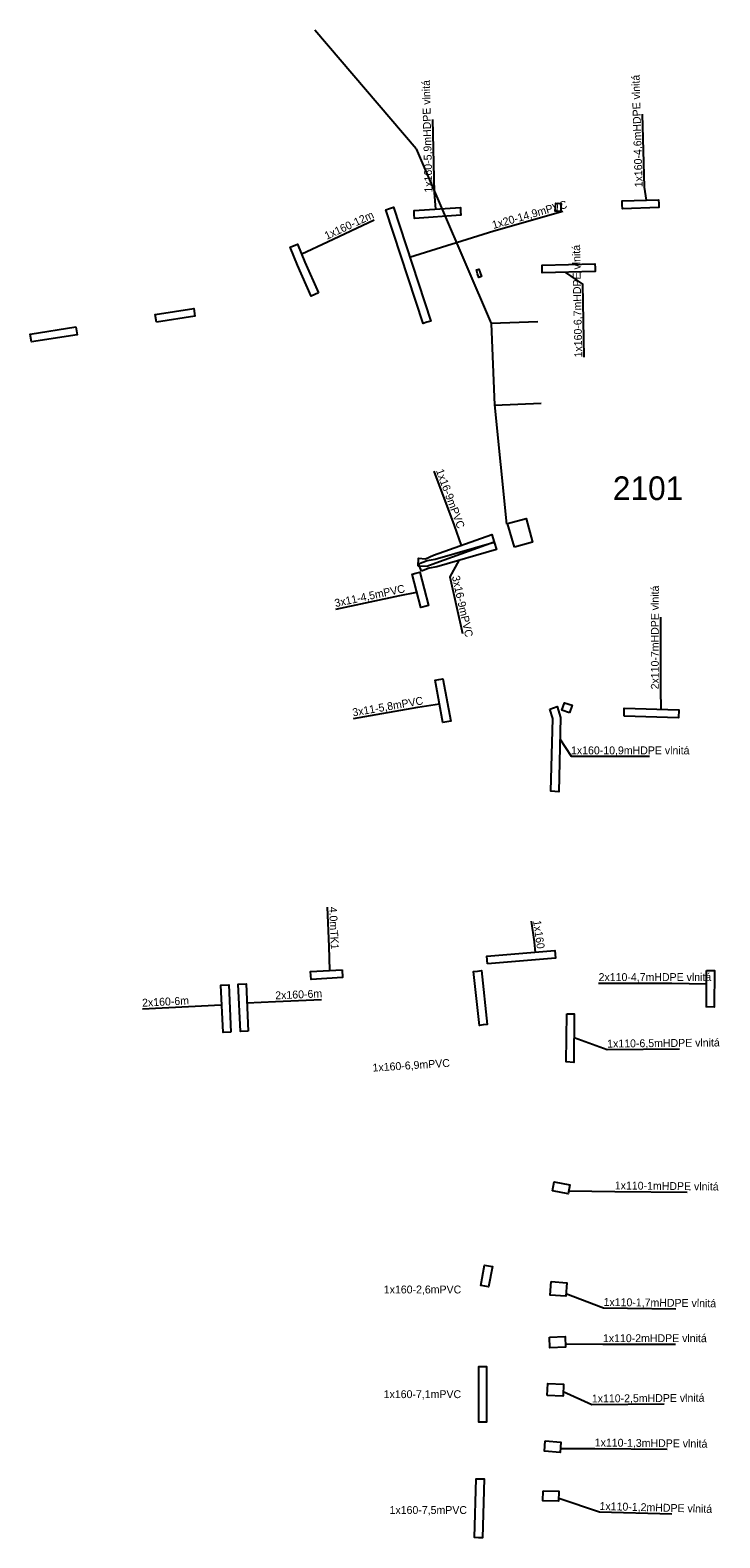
# Model space of a CAD drawing. Extents: x -732155 to -731960, y -1048709 to -1047981.
# Drawn here: x -732047.3 to -731959.9, y -1048709 to -1048517.8 of the extents above; entities that cross this region are included whole.
import ezdxf

# ---------------------------------------------------------------- set-up
doc = ezdxf.new("R2010")
doc.units = 0
for name, color, linetype in [('Chránička', 7, 'Continuous'), ('ST_CHRANICKA_POPIS', 7, 'Continuous'), ('ST_OBECNA_STAVBA', 7, 'Continuous'), ('ST_TRAFOSTANICE_POPIS', 7, 'Continuous'), ('TS_RS_R', 7, 'Continuous')]:
    doc.layers.add(name, color=color, linetype=linetype)

msp = doc.modelspace()

# ---------------------------------------------------------------- linework, layer by layer
at = {"layer": 'Chránička'}
for points in [[(-732001.75, -1048540.433), (-732001.275, -1048540.277), (-731996.545, -1048554.697), (-731997.02, -1048554.853), (-731997.495, -1048555.009), (-732002.225, -1048540.589), (-732001.75, -1048540.433)], [(-731992.76, -1048540.79), (-731992.727, -1048541.289), (-731998.597, -1048541.679), (-731998.63, -1048541.18), (-731998.663, -1048540.681), (-731992.793, -1048540.291), (-731992.76, -1048540.79)], [(-731980.05, -1048540.31), (-731980.079, -1048540.809), (-731980.769, -1048540.769), (-731980.74, -1048540.27), (-731980.711, -1048539.771), (-731980.021, -1048539.811), (-731980.05, -1048540.31)], [(-731972.27, -1048539.97), (-731972.286, -1048539.47), (-731967.676, -1048539.32), (-731967.66, -1048539.82), (-731967.644, -1048540.32), (-731972.254, -1048540.47), (-731972.27, -1048539.97)], [(-732010.76, -1048551.133), (-732011.674, -1048551.539), (-732013.415, -1048547.613), (-732014.366, -1048545.313), (-732013.442, -1048544.931), (-732012.495, -1048547.219), (-732010.76, -1048551.133)], [(-731990.27, -1048548.58), (-731990.108, -1048549.053), (-731990.438, -1048549.166), (-731990.6, -1048548.693), (-731990.762, -1048548.22), (-731990.432, -1048548.107), (-731990.27, -1048548.58)], [(-731975.73, -1048547.933), (-731975.717, -1048548.433), (-731982.417, -1048548.603), (-731982.43, -1048548.103), (-731982.443, -1048547.603), (-731975.743, -1048547.433), (-731975.73, -1048547.933)], [(-732031.296, -1048554.856), (-732031.45, -1048553.868), (-732026.57, -1048553.103), (-732026.416, -1048554.091), (-732031.296, -1048554.856)], [(-732041.497, -1048555.442), (-732041.343, -1048556.43), (-732047.145, -1048557.339), (-732047.299, -1048556.351), (-732041.497, -1048555.442)], [(-731998.138, -1048585.78), (-731998.102, -1048584.78), (-731997.225, -1048584.864), (-731996.188, -1048584.399), (-731988.798, -1048581.769), (-731988.51, -1048582.73), (-731995.9, -1048585.4), (-731997.038, -1048585.82), (-731998.138, -1048585.78)], [(-731997.707, -1048586.431), (-731998.093, -1048585.509), (-731996.997, -1048585.066), (-731995.977, -1048584.906), (-731988.51, -1048582.73), (-731988.23, -1048583.69), (-731995.76, -1048585.88), (-731996.727, -1048586.021), (-731997.707, -1048586.431)], [(-731997.31, -1048590.88), (-731997.793, -1048591.008), (-731998.903, -1048586.808), (-731998.42, -1048586.68), (-731997.937, -1048586.552), (-731996.827, -1048590.752), (-731997.31, -1048590.88)], [(-731995.5, -1048600.17), (-731995.008, -1048600.079), (-731994.018, -1048605.429), (-731994.51, -1048605.52), (-731995.002, -1048605.611), (-731995.992, -1048600.261), (-731995.5, -1048600.17)], [(-731981.468, -1048603.929), (-731980.532, -1048603.574), (-731980.088, -1048604.958), (-731980.329, -1048614.388), (-731981.328, -1048614.324), (-731981.092, -1048605.102), (-731981.468, -1048603.929)], [(-731978.964, -1048604.372), (-731979.914, -1048604.042), (-731979.586, -1048603.098), (-731978.636, -1048603.428), (-731978.964, -1048604.372)], [(-731972.046, -1048604.79), (-731972.014, -1048603.79), (-731965.104, -1048604.01), (-731965.136, -1048605.01), (-731972.046, -1048604.79)], [(-731989.373, -1048636.234), (-731989.457, -1048635.238), (-731980.818, -1048634.509), (-731980.734, -1048635.505), (-731989.373, -1048636.234)], [(-732007.766, -1048636.963), (-732007.71, -1048637.961), (-732011.704, -1048638.186), (-732011.76, -1048637.188), (-732007.766, -1048636.963)], [(-731990.63, -1048637.13), (-731990.133, -1048637.075), (-731989.383, -1048643.905), (-731989.88, -1048643.96), (-731990.377, -1048644.015), (-731991.127, -1048637.185), (-731990.63, -1048637.13)], [(-731961.59, -1048637.053), (-731960.59, -1048637.05), (-731960.62, -1048641.691), (-731961.634, -1048641.681), (-731961.62, -1048641.625), (-731961.59, -1048637.053)], [(-732021.863, -1048644.875), (-732022.861, -1048644.921), (-732023.137, -1048638.927), (-732022.139, -1048638.881), (-732021.863, -1048644.875)], [(-732019.669, -1048644.731), (-732020.667, -1048644.777), (-732020.943, -1048638.783), (-732019.945, -1048638.737), (-732019.669, -1048644.731)], [(-731979.318, -1048642.57), (-731978.371, -1048642.57), (-731978.399, -1048648.72), (-731979.39, -1048648.66), (-731979.318, -1048642.57)], [(-731981.113, -1048665.008), (-731980.905, -1048663.876), (-731978.937, -1048664.238), (-731979.145, -1048665.37), (-731981.113, -1048665.008)], [(-731989.23, -1048674.5), (-731988.738, -1048674.591), (-731989.218, -1048677.171), (-731989.71, -1048677.08), (-731990.202, -1048676.989), (-731989.722, -1048674.409), (-731989.23, -1048674.5)], [(-731981.29, -1048676.515), (-731979.296, -1048676.661), (-731979.421, -1048678.377), (-731981.415, -1048678.231), (-731981.29, -1048676.515)], [(-731981.504, -1048683.564), (-731979.506, -1048683.486), (-731979.454, -1048684.813), (-731981.452, -1048684.891), (-731981.504, -1048683.564)], [(-731989.96, -1048687.26), (-731989.46, -1048687.26), (-731989.46, -1048694.35), (-731989.96, -1048694.35), (-731990.46, -1048694.35), (-731990.46, -1048687.26), (-731989.96, -1048687.26)], [(-731981.792, -1048690.97), (-731981.723, -1048689.412), (-731979.725, -1048689.5), (-731979.762, -1048690.951), (-731979.794, -1048691.058), (-731981.792, -1048690.97)], [(-731982.049, -1048696.712), (-731980.055, -1048696.864), (-731980.155, -1048698.175), (-731982.149, -1048698.023), (-731982.049, -1048696.712)], [(-731990.27, -1048701.52), (-731989.77, -1048701.535), (-731990, -1048709.005), (-731990.5, -1048708.99), (-731991, -1048708.975), (-731990.77, -1048701.505), (-731990.27, -1048701.52)], [(-731982.314, -1048703.034), (-731980.314, -1048703.066), (-731980.335, -1048704.345), (-731982.335, -1048704.313), (-731982.314, -1048703.034)]]:
    msp.add_lwpolyline(points, close=True, dxfattribs=at)
at = {"layer": 'ST_CHRANICKA_POPIS'}
for points in [[(-731995.885, -1048540.496), (-731996.077, -1048538.394), (-731996.292, -1048529.133)], [(-731969.22, -1048539.37), (-731969.439, -1048537.717), (-731969.702, -1048528.457)], [(-732012.875, -1048546.195), (-732009.608, -1048544.637), (-732003.697, -1048541.886)], [(-731999.246, -1048546.581), (-731988.536, -1048543.269), (-731979.826, -1048540.781)], [(-731977.087, -1048559.296), (-731977.272, -1048550.034), (-731979.42, -1048548.527)], [(-731996.139, -1048573.75), (-731993.578, -1048580.632), (-731992.678, -1048583.15)], [(-731992.983, -1048585.072), (-731994.118, -1048587.157), (-731992.516, -1048594.323)], [(-732008.556, -1048591.228), (-732000.46, -1048589.49), (-731998.307, -1048589.063)], [(-731967.364, -1048603.938), (-731967.398, -1048601.407), (-731967.394, -1048592.235)], [(-732006.331, -1048605.089), (-731998.172, -1048603.672), (-731995.442, -1048603.233)], [(-731980.173, -1048607.676), (-731978.77, -1048609.895), (-731968.82, -1048609.895)], [(-732009.678, -1048629.008), (-732009.452, -1048634.013), (-732009.351, -1048637.027)], [(-731983.832, -1048630.79), (-731983.453, -1048633.441), (-731983.297, -1048634.777)], [(-731975.271, -1048638.645), (-731966.008, -1048638.645), (-731961.596, -1048638.763)], [(-732033.08, -1048641.907), (-732027.254, -1048641.605), (-732023.101, -1048641.424)], [(-732019.844, -1048641.165), (-732016.214, -1048640.972), (-732010.385, -1048640.717)], [(-731978.385, -1048645.551), (-731974.182, -1048647.08), (-731965.01, -1048646.988)], [(-731979.059, -1048665.007), (-731973.227, -1048665.064), (-731964.056, -1048665.163)], [(-731979.413, -1048678.036), (-731974.653, -1048679.849), (-731965.482, -1048679.959)], [(-731979.47, -1048684.399), (-731974.723, -1048684.439), (-731965.551, -1048684.439)], [(-731979.768, -1048690.461), (-731976.125, -1048692.083), (-731966.953, -1048692.027)], [(-731980.116, -1048697.669), (-731975.769, -1048697.659), (-731966.597, -1048697.761)], [(-731980.329, -1048703.985), (-731975.171, -1048705.718), (-731966.003, -1048705.96)]]:
    msp.add_lwpolyline(points, dxfattribs=at)
at = {"layer": 'ST_OBECNA_STAVBA'}
for p, q in [((-731998.37, -1048532.85), (-732011.217, -1048517.812)), ((-731998.37, -1048532.85), (-731988.88, -1048555.02)), ((-731988.484, -1048565.325), (-731986.938, -1048580.449))]:
    msp.add_line(p, q, dxfattribs=at)
msp.add_lwpolyline([(-731982.966, -1048554.791), (-731988.88, -1048555.02), (-731988.48, -1048565.36), (-731982.566, -1048565.131)], dxfattribs=at)
at = {"layer": 'TS_RS_R'}
msp.add_lwpolyline([(-731985.95, -1048583.38), (-731986.8, -1048580.37), (-731984.47, -1048579.73), (-731983.67, -1048582.76), (-731985.95, -1048583.38)], close=True, dxfattribs=at)

# ---------------------------------------------------------------- texts
at = {"layer": 'ST_CHRANICKA_POPIS'}
for s, rotation, p in [('1x160-5,9mHDPE vlnitá', 91.32799, (-731996.327, -1048538.4)), ('1x160-4,6mHDPE vlnitá', 91.62768, (-731969.689, -1048537.724)), ('1x20-14,9mPVC', 15.94062, (-731988.605, -1048543.029)), ('1x160-12m', 24.95485, (-732009.714, -1048544.41)), ('1x160-6,7mHDPE vlnitá', 91.14742, (-731977.337, -1048559.301)), ('1x16-9mPVC', 290.40876, (-731995.904, -1048573.663)), ('3x11-4,5mPVC', 12.11768, (-732008.609, -1048590.984)), ('3x16-9mPVC', 282.59705, (-731993.874, -1048587.103)), ('2x110-7mHDPE vlnitá', 89.98048, (-731967.648, -1048601.407)), ('3x11-5,8mPVC', 9.85203, (-732006.374, -1048604.843)), ('4.0mTK1', 272.57825, (-732009.428, -1048628.997)), ('1x160', 278.13237, (-731983.584, -1048630.755)), ('2x160-6m', 2.50595, (-732016.224, -1048640.722)), ('2x160-6m', 2.96623, (-732033.093, -1048641.657)), ('1x110-6,5mHDPE vlnitá', 0.572, (-731974.184, -1048646.83)), ('1x160-6,9mPVC', 3.58748, (-732003.884, -1048649.885)), ('1x110-1mHDPE vlnitá', 359.38389, (-731973.224, -1048664.814)), ('1x110-1,7mHDPE vlnitá', 359.30853, (-731974.65, -1048679.599)), ('1x110-2,5mHDPE vlnitá', 0.351, (-731976.126, -1048691.833)), ('1x110-1,3mHDPE vlnitá', 359.36475, (-731975.766, -1048697.409)), ('1x110-1,2mHDPE vlnitá', 358.48728, (-731975.165, -1048705.468))]:
    msp.add_text(s, height=1, rotation=rotation, dxfattribs=at).set_placement(p)
for s, p in [('1x160-10,9mHDPE vlnitá', (-731978.77, -1048609.645)), ('2x110-4,7mHDPE vlnitá', (-731975.271, -1048638.395)), ('1x160-2,6mPVC', (-732002.491, -1048678.009)), ('1x110-2mHDPE vlnitá', (-731974.723, -1048684.189)), ('1x160-7,1mPVC', (-732002.506, -1048691.286)), ('1x160-7,5mPVC', (-732001.762, -1048705.976))]:
    msp.add_text(s, height=1, dxfattribs=at).set_placement(p)
at = {"layer": 'ST_TRAFOSTANICE_POPIS'}
msp.add_text('2101', height=3, dxfattribs=at).set_placement((-731973.469, -1048577.398))

doc.saveas('drawing.dxf')
